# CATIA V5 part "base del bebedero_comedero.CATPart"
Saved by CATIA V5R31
Part number: base del bebedero_comedero
Bounding box of the stored display mesh (mm): x -127.5 to 127.5, y -186.6 to 90, z 0 to 3.3
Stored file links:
  C:\Users\189361\Desktop\base del bebedero_comedero.CATPart
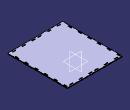
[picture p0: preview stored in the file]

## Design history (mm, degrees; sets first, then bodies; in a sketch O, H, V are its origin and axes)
Set1 "sketch"
  Sketch1 on xy-plane, origin (0, 0, 0), H (1, 0, 0), V (0, 1, 0)
    construction circle A1 centre (0, -59.1) radius 112.5
    point P1 (0, -59.1)
    line L1 (-127.5, 90) -> (127.5, 90)
    line L2 (127.5, 90) -> (127.5, -186.6)
    line L3 (127.5, -186.6) -> (-127.5, -186.6)
    line L4 (-127.5, -186.6) -> (-127.5, 90)
    point P6 (0, 8.4)
    construction circle A2 centre (0, 8.4) radius 15
    construction line L5 (75, 83.4) -> (75, -66.6)
    construction line L6 (75, -66.6) -> (-75, -66.6)
    construction line L7 (-75, -66.6) -> (-75, 83.4)
    construction line L8 (-75, 83.4) -> (75, 83.4)
    construction circle A3 centre (0, -59.1) radius 97.5
    radius A1 = 112.5
    radius A2 = 15
    length L8 = 150
    distance A3 A1 V = 15
    distance L8 L1 = 6.6
    distance H L1 = 90
    distance A2 A3 = 15
    distance A1 L2 = 15
    distance L4 A1 = 15
    distance L3 A1 = 15
    length L4 = 276.6 (reference)
    coincidence: P1 V, P6 V
    horizontal: L3 H, L6 H, L8 H
    vertical: L2 V, L4 V, L5 V, L7 V
    equidistance: L5 L7 P6, L6 L8 P6
    equal size: L5 L8, L2 L4, L3 L1
  Sketch2 on end face of Pad1, origin (0, 0, 3.3), H (1, 0, 0), V (0, 1, 0)
    construction circle A1 centre (0, -59.1) radius 97.5
    construction circle A2 centre (0, -59.1) radius 112.5
    construction line L1 (75, -66.6) -> (-75, -66.6)
    construction circle A3 centre (0, 8.4) radius 15
    point P5 (122.55, 77.5)
    line L2 (124.05, 85) -> (124.05, 70)
    line L3 (124.05, 70) -> (121.05, 70)
    line L4 (121.05, 70) -> (121.05, 85)
    line L5 (121.05, 85) -> (124.05, 85)
    point P6 (124.05, 85)
    point P7 (124.05, 70)
    point P8 (121.05, 70)
    point P9 (121.05, 85)
    construction line L6 (75, 83.4) -> (75, -66.6)
    construction line L7 (-75, 83.4) -> (75, 83.4)
    construction line L8 (-75, -66.6) -> (-75, 83.4)
    construction line L9 (122.55, 27.8343) -> (122.55, 77.723)
    point P14 (122.55, 27.8343)
    point P15 (122.55, 77.723)
    reference projected line E1 (127.5, -186.6) -> (127.5, 90) from edge [face of Pad1 from Sketch1.L2 | end face of Pad1]
    reference projected line E2 (127.5, 90) -> (-127.5, 90) from edge [face of Pad1 from Sketch1.L1 | end face of Pad1]
    construction line L10 (91.0576, 55) -> (155.1639, 55)
    point P18 (124.05, 40)
    point P19 (124.05, 25)
    line L11 (124.05, 25) -> (124.05, 40)
    point P20 (121.05, 40)
    line L12 (124.05, 40) -> (121.05, 40)
    point P21 (121.05, 25)
    line L13 (121.05, 40) -> (121.05, 25)
    line L14 (121.05, 25) -> (124.05, 25)
    construction line L15 (196.6068, -80) -> (-170.4022, -80)
    axis line L16 (177.1238, 10) -> (115.6704, 10)
    point P25 (115.6704, 10)
    point P26 (124.05, -20)
    point P27 (124.05, -5)
    line L17 (124.05, -5) -> (124.05, -20)
    point P28 (121.05, -5)
    line L18 (121.05, -5) -> (124.05, -5)
    point P29 (121.05, -20)
    line L19 (121.05, -20) -> (121.05, -5)
    line L20 (124.05, -20) -> (121.05, -20)
    point P30 (121.05, -50)
    point P31 (124.05, -50)
    line L21 (124.05, -50) -> (121.05, -50)
    point P32 (124.05, -65)
    line L22 (124.05, -65) -> (124.05, -50)
    point P33 (121.05, -65)
    line L23 (121.05, -50) -> (121.05, -65)
    line L24 (121.05, -65) -> (124.05, -65)
    point P34 (124.05, -95)
    point P35 (121.05, -95)
    line L25 (121.05, -95) -> (124.05, -95)
    point P36 (121.05, -110)
    line L26 (121.05, -110) -> (121.05, -95)
    point P37 (124.05, -110)
    line L27 (124.05, -95) -> (124.05, -110)
    line L28 (124.05, -110) -> (121.05, -110)
    point P38 (121.05, -140)
    point P39 (124.05, -140)
    line L29 (124.05, -140) -> (121.05, -140)
    point P40 (121.05, -155)
    line L30 (121.05, -140) -> (121.05, -155)
    point P41 (124.05, -155)
    line L31 (124.05, -155) -> (124.05, -140)
    line L32 (121.05, -155) -> (124.05, -155)
    point P42 (-122.55, 77.5)
    point P43 (-124.05, 85)
    point P44 (-124.05, 70)
    point P45 (-121.05, 70)
    point P46 (-121.05, 85)
    point P47 (-122.55, 77.723)
    point P48 (-122.55, 27.8343)
    construction line L33 (-122.55, 27.8343) -> (-122.55, 77.723)
    point P49 (-124.05, 40)
    point P50 (-124.05, 25)
    point P51 (-121.05, 40)
    point P52 (-121.05, 25)
    point P53 (-115.6704, 10)
    point P54 (-124.05, -20)
    point P55 (-124.05, -5)
    point P56 (-121.05, -5)
    point P57 (-121.05, -20)
    point P58 (-121.05, -50)
    point P59 (-124.05, -50)
    point P60 (-124.05, -65)
    point P61 (-121.05, -65)
    point P62 (-124.05, -95)
    point P63 (-121.05, -95)
    point P64 (-121.05, -110)
    point P65 (-124.05, -110)
    point P66 (-121.05, -140)
    point P67 (-124.05, -140)
    point P68 (-121.05, -155)
    point P69 (-124.05, -155)
    line L34 (-124.05, 85) -> (-124.05, 70)
    line L35 (-124.05, 70) -> (-121.05, 70)
    line L36 (-121.05, 70) -> (-121.05, 85)
    line L37 (-121.05, 85) -> (-124.05, 85)
    line L38 (-124.05, 25) -> (-124.05, 40)
    line L39 (-124.05, 40) -> (-121.05, 40)
    line L40 (-121.05, 40) -> (-121.05, 25)
    line L41 (-121.05, 25) -> (-124.05, 25)
    line L42 (-124.05, -5) -> (-124.05, -20)
    line L43 (-121.05, -5) -> (-124.05, -5)
    line L44 (-121.05, -20) -> (-121.05, -5)
    line L45 (-124.05, -20) -> (-121.05, -20)
    line L46 (-124.05, -50) -> (-121.05, -50)
    line L47 (-124.05, -65) -> (-124.05, -50)
    line L48 (-121.05, -50) -> (-121.05, -65)
    line L49 (-121.05, -65) -> (-124.05, -65)
    line L50 (-121.05, -95) -> (-124.05, -95)
    line L51 (-121.05, -110) -> (-121.05, -95)
    line L52 (-124.05, -95) -> (-124.05, -110)
    line L53 (-124.05, -110) -> (-121.05, -110)
    line L54 (-124.05, -140) -> (-121.05, -140)
    line L55 (-121.05, -140) -> (-121.05, -155)
    line L56 (-124.05, -155) -> (-124.05, -140)
    line L57 (-121.05, -155) -> (-124.05, -155)
    length L5 = 3
    length L2 = 15
    distance L4 L9 = 1.5
    distance L9 E1 = 4.95
    distance L5 E2 = 5
    distance L10 L3 = 15
    distance L16 L14 = 15
    distance L15 L24 = 15
    vertical: L2 V, L4 V, L9 V
    horizontal: L3 H, L5 H, L10 H, L15 H, L16 H
    equidistance: L2 L4 P5, L3 L5 P5
    symmetry: P7 P18 L10, P6 P19 L10, L2 L11 L10, P8 P20 L10, L3 L12 L10, P9 P21 L10, L4 L13 L10, L5 L14 L10, P18 P26 L16, P19 P27 L16, L11 L17 L16, P21 P28 L16, L14 L18 L16, P20 P29 L16, L13 L19 L16, L12 L20 L16, P8 P30 L16, P7 P31 L16, L3 L21 L16, P6 P32 L16, L2 L22 L16, P9 P33 L16, L4 L23 L16, L5 L24 L16, P32 P34 L15, P33 P35 L15, L24 L25 L15, P30 P36 L15, L23 L26 L15, P31 P37 L15, L22 L27 L15, L21 L28 L15, P29 P38 L15, P26 P39 L15, L20 L29 L15, P28 P40 L15, L19 L30 L15, P27 P41 L15, L17 L31 L15, L18 L32 L15, P5 P42 V, P6 P43 V, P7 P44 V, P8 P45 V, P9 P46 V, P15 P47 V, P14 P48 V, L9 L33 V, P18 P49 V, P19 P50 V, P20 P51 V, P21 P52 V, P25 P53 V, P26 P54 V, P27 P55 V, P28 P56 V, P29 P57 V, P30 P58 V, P31 P59 V, P32 P60 V, P33 P61 V, P34 P62 V, P35 P63 V, P36 P64 V, P37 P65 V, P38 P66 V, P39 P67 V, P40 P68 V, P41 P69 V, L2 L34 V, L3 L35 V, L4 L36 V, L5 L37 V, L11 L38 V, L12 L39 V, L13 L40 V, L14 L41 V, L17 L42 V, L18 L43 V, L19 L44 V, L20 L45 V, L21 L46 V, L22 L47 V, L23 L48 V, L24 L49 V, L25 L50 V, L26 L51 V, L27 L52 V, L28 L53 V, L29 L54 V, L30 L55 V, L31 L56 V, L32 L57 V
  Sketch3 on end face of Pad1, origin (0, 0, 3.3), H (1, 0, 0), V (0, 1, 0)
    point P1 (-111.05, 85.2)
    line L1 (-111.05, 85.2) -> (-96.05, 85.2)
    line L2 (-96.05, 85.2) -> (-96.05, 82.2)
    line L3 (-96.05, 82.2) -> (-111.05, 82.2)
    line L4 (-111.05, 82.2) -> (-111.05, 85.2)
    point P2 (-96.05, 85.2)
    point P3 (-96.05, 82.2)
    point P4 (-111.05, 82.2)
    construction line L5 (-131.5186, 83.7) -> (-92.6292, 83.7)
    point P5 (-131.5186, 83.7)
    point P6 (-92.6292, 83.7)
    reference projected line E1 (127.5, 90) -> (-127.5, 90) from edge [face of Pad1 from Sketch1.L1 | end face of Pad1]
    reference projected line E2 (-121.05, 70) -> (-121.05, 85) from edge [end face of Pad1 | face of Pocket1 from Sketch2.L36]
    construction line L6 (-81.05, 98.7519) -> (-81.05, 65.1098)
    point P7 (-81.05, 98.7519)
    point P8 (-81.05, 65.1098)
    point P9 (-51.05, 85.2)
    point P10 (-66.05, 85.2)
    point P11 (-66.05, 82.2)
    point P12 (-51.05, 82.2)
    line L7 (-51.05, 85.2) -> (-66.05, 85.2)
    line L8 (-66.05, 85.2) -> (-66.05, 82.2)
    line L9 (-66.05, 82.2) -> (-51.05, 82.2)
    line L10 (-51.05, 82.2) -> (-51.05, 85.2)
    construction line L11 (-36.05, 99.5135) -> (-36.05, 74.2503)
    point P13 (-36.05, 99.5135)
    point P14 (-36.05, 74.2503)
    point P15 (-21.05, 85.2)
    point P16 (-6.05, 85.2)
    point P17 (-6.05, 82.2)
    point P18 (-21.05, 82.2)
    line L12 (-21.05, 85.2) -> (-6.05, 85.2)
    line L13 (-6.05, 85.2) -> (-6.05, 82.2)
    line L14 (-6.05, 82.2) -> (-21.05, 82.2)
    line L15 (-21.05, 82.2) -> (-21.05, 85.2)
    point P19 (111.05, 85.2)
    point P20 (96.05, 85.2)
    point P21 (96.05, 82.2)
    point P22 (111.05, 82.2)
    point P23 (92.6292, 83.7)
    point P24 (51.05, 85.2)
    point P25 (66.05, 85.2)
    point P26 (66.05, 82.2)
    point P27 (51.05, 82.2)
    point P28 (21.05, 85.2)
    point P29 (6.05, 85.2)
    point P30 (6.05, 82.2)
    point P31 (21.05, 82.2)
    line L16 (111.05, 85.2) -> (96.05, 85.2)
    line L17 (96.05, 85.2) -> (96.05, 82.2)
    line L18 (96.05, 82.2) -> (111.05, 82.2)
    line L19 (111.05, 82.2) -> (111.05, 85.2)
    line L20 (51.05, 85.2) -> (66.05, 85.2)
    line L21 (66.05, 85.2) -> (66.05, 82.2)
    line L22 (66.05, 82.2) -> (51.05, 82.2)
    line L23 (51.05, 82.2) -> (51.05, 85.2)
    line L24 (21.05, 85.2) -> (6.05, 85.2)
    line L25 (6.05, 85.2) -> (6.05, 82.2)
    line L26 (6.05, 82.2) -> (21.05, 82.2)
    line L27 (21.05, 82.2) -> (21.05, 85.2)
    axis line L28 (170.5942, -48.3) -> (-250.7207, -48.3)
    point P34 (-111.05, -181.8)
    point P35 (-96.05, -181.8)
    point P36 (-96.05, -178.8)
    point P37 (-111.05, -178.8)
    point P38 (-92.6292, -180.3)
    point P39 (-131.5186, -180.3)
    construction line L29 (-131.5186, -180.3) -> (-92.6292, -180.3)
    point P40 (-81.05, -161.7098)
    point P41 (-81.05, -195.3519)
    construction line L30 (-81.05, -195.3519) -> (-81.05, -161.7098)
    point P42 (-51.05, -181.8)
    point P43 (-66.05, -181.8)
    point P44 (-66.05, -178.8)
    point P45 (-51.05, -178.8)
    point P46 (-36.05, -170.8503)
    point P47 (-36.05, -196.1135)
    construction line L31 (-36.05, -196.1135) -> (-36.05, -170.8503)
    point P48 (-21.05, -181.8)
    point P49 (-6.05, -181.8)
    point P50 (-6.05, -178.8)
    point P51 (-21.05, -178.8)
    point P52 (111.05, -181.8)
    point P53 (96.05, -181.8)
    point P54 (96.05, -178.8)
    point P55 (111.05, -178.8)
    point P56 (92.6292, -180.3)
    point P57 (51.05, -181.8)
    point P58 (66.05, -181.8)
    point P59 (66.05, -178.8)
    point P60 (51.05, -178.8)
    point P61 (21.05, -181.8)
    point P62 (6.05, -181.8)
    point P63 (6.05, -178.8)
    point P64 (21.05, -178.8)
    line L32 (-111.05, -181.8) -> (-96.05, -181.8)
    line L33 (-96.05, -181.8) -> (-96.05, -178.8)
    line L34 (-96.05, -178.8) -> (-111.05, -178.8)
    line L35 (-111.05, -178.8) -> (-111.05, -181.8)
    line L36 (-51.05, -181.8) -> (-66.05, -181.8)
    line L37 (-66.05, -181.8) -> (-66.05, -178.8)
    line L38 (-66.05, -178.8) -> (-51.05, -178.8)
    line L39 (-51.05, -178.8) -> (-51.05, -181.8)
    line L40 (-21.05, -181.8) -> (-6.05, -181.8)
    line L41 (-6.05, -181.8) -> (-6.05, -178.8)
    line L42 (-6.05, -178.8) -> (-21.05, -178.8)
    line L43 (-21.05, -178.8) -> (-21.05, -181.8)
    line L44 (111.05, -181.8) -> (96.05, -181.8)
    line L45 (96.05, -181.8) -> (96.05, -178.8)
    line L46 (96.05, -178.8) -> (111.05, -178.8)
    line L47 (111.05, -178.8) -> (111.05, -181.8)
    line L48 (51.05, -181.8) -> (66.05, -181.8)
    line L49 (66.05, -181.8) -> (66.05, -178.8)
    line L50 (66.05, -178.8) -> (51.05, -178.8)
    line L51 (51.05, -178.8) -> (51.05, -181.8)
    line L52 (21.05, -181.8) -> (6.05, -181.8)
    line L53 (6.05, -181.8) -> (6.05, -178.8)
    line L54 (6.05, -178.8) -> (21.05, -178.8)
    line L55 (21.05, -178.8) -> (21.05, -181.8)
    reference projected line E3 (-124.05, -140) -> (-124.05, -155) from edge [end face of Pad1 | face of Pocket1 from Sketch2.L56]
    reference projected line E4 (124.05, -155) -> (124.05, -140) from edge [end face of Pad1 | face of Pocket1 from Sketch2.L31]
    reference projected line E5 (-121.05, -155) -> (-121.05, -140) from edge [end face of Pad1 | face of Pocket1 from Sketch2.L55]
    reference projected line E6 (121.05, -140) -> (121.05, -155) from edge [end face of Pad1 | face of Pocket1 from Sketch2.L30]
    length L4 = 3
    distance L5 L1 = 1.5
    distance L1 E1 = 4.8
    distance L4 E2 = 10
    length L1 = 15
    distance L2 L6 = 15
    distance L11 L10 = 15
    distance L28 E1 = 138.3
    distance L16 L46 = 264 (reference)
    distance E3 E4 = 248.1 (reference)
    distance L41 V = 6.05 (reference)
    distance E5 E6 = 242.1 (reference)
    distance L53 V = 6.05 (reference)
    horizontal: L1 H, L3 H, L5 H, L28 H
    vertical: L2 V, L4 V, L6 V, L11 V
    symmetry: P1 P9 L6, P2 P10 L6, P3 P11 L6, P4 P12 L6, L1 L7 L6, L2 L8 L6, L3 L9 L6, L4 L10 L6, P9 P15 L11, P10 P16 L11, P11 P17 L11, P12 P18 L11, L7 L12 L11, L8 L13 L11, L9 L14 L11, L10 L15 L11, P1 P19 V, P2 P20 V, P3 P21 V, P4 P22 V, P6 P23 V, P9 P24 V, P10 P25 V, P11 P26 V, P12 P27 V, P15 P28 V, P16 P29 V, P17 P30 V, P18 P31 V, L1 L16 V, L2 L17 V, L3 L18 V, L4 L19 V, L7 L20 V, L8 L21 V, L9 L22 V, L10 L23 V, L12 L24 V, L13 L25 V, L14 L26 V, L15 L27 V, P1 P34 L28, P2 P35 L28, P3 P36 L28, P4 P37 L28, P6 P38 L28, P5 P39 L28, L5 L29 L28, P8 P40 L28, P7 P41 L28, L6 L30 L28, P9 P42 L28, P10 P43 L28, P11 P44 L28, P12 P45 L28, P14 P46 L28, P13 P47 L28, L11 L31 L28, P15 P48 L28, P16 P49 L28, P17 P50 L28, P18 P51 L28, P19 P52 L28, P20 P53 L28, P21 P54 L28, P22 P55 L28, P23 P56 L28, P24 P57 L28, P25 P58 L28, P26 P59 L28, P27 P60 L28, P28 P61 L28, P29 P62 L28, P30 P63 L28, P31 P64 L28, L1 L32 L28, L2 L33 L28, L3 L34 L28, L4 L35 L28, L7 L36 L28, L8 L37 L28, L9 L38 L28, L10 L39 L28, L12 L40 L28, L13 L41 L28, L14 L42 L28, L15 L43 L28, L16 L44 L28, L17 L45 L28, L18 L46 L28, L19 L47 L28, L20 L48 L28, L21 L49 L28, L22 L50 L28, L23 L51 L28, L24 L52 L28, L25 L53 L28, L26 L54 L28, L27 L55 L28
Body1 (main body)
  Pad1: profile Sketch1, direction (0, 0, 1), length 3.3
  Pocket1: profile Sketch2, direction (0, 0, -1), length 3.3
  Pocket2: profile Sketch3, direction (0, 0, -1), length 3.3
